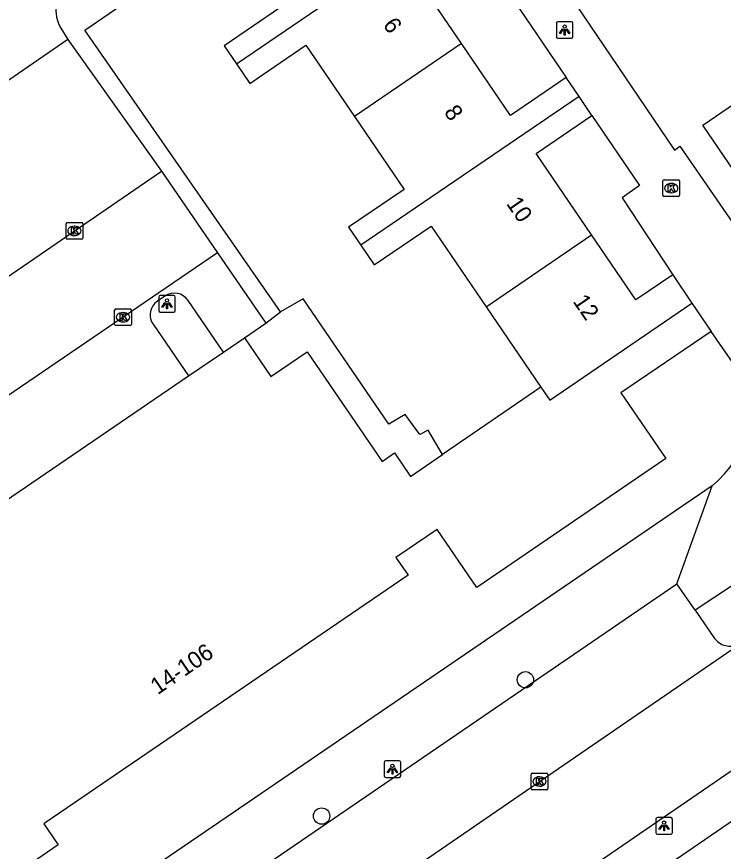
# Model space of a CAD drawing. Extents: x 157466 to 158888, y 383063 to 384677.
# Drawn here: x 158400.9 to 158443.3, y 383786.1 to 383836.2 of the extents above; entities that cross this region are included whole.
import ezdxf

# ---------------------------------------------------------------- set-up
doc = ezdxf.new("R2010")
doc.units = 0
for name, color, linetype in [('IMGEO_Boom', 7, 'Continuous'), ('IMGEO_Kolk', 7, 'Continuous'), ('IMGEO_Lichtpunt', 7, 'Continuous'), ('IMGEO_Pand', 7, 'Continuous'), ('IMGEO_Pand_nummerreeks', 7, 'Continuous'), ('IMGEO_Parkeervlak_open', 7, 'Continuous'), ('IMGEO_Rijbaan_lokaal_open', 7, 'Continuous'), ('IMGEO_Voetpad_open', 7, 'Continuous')]:
    doc.layers.add(name, color=color, linetype=linetype)

msp = doc.modelspace()

# ---------------------------------------------------------------- linework, layer by layer
at = {"layer": 'IMGEO_Boom'}
for centre in [(158431.47, 383796.371), (158419.242, 383788.198)]:
    msp.add_circle(centre, 0.489, dxfattribs=at)
at = {"layer": 'IMGEO_Kolk'}
for p, q in [((158439.718, 383825.444), (158439.718, 383826.296)), ((158439.793, 383826.37), (158440.645, 383826.37)), ((158440.206, 383826.15), (158440.231, 383826.15)), ((158440.719, 383826.296), (158440.719, 383825.444)), ((158440.229, 383825.59), (158440.204, 383825.59)), ((158440.645, 383825.37), (158439.793, 383825.37)), ((158403.906, 383822.873), (158403.906, 383823.725)), ((158403.981, 383823.799), (158404.833, 383823.799)), ((158404.394, 383823.579), (158404.419, 383823.579)), ((158404.907, 383823.725), (158404.907, 383822.873)), ((158404.417, 383823.019), (158404.392, 383823.019)), ((158404.833, 383822.799), (158403.981, 383822.799)), ((158406.823, 383817.693), (158406.823, 383818.545)), ((158406.898, 383818.619), (158407.75, 383818.619)), ((158407.824, 383818.545), (158407.824, 383817.693)), ((158407.311, 383818.399), (158407.336, 383818.399)), ((158407.75, 383817.619), (158406.898, 383817.619)), ((158407.334, 383817.839), (158407.309, 383817.839)), ((158431.814, 383789.845), (158431.814, 383790.697)), ((158431.889, 383790.771), (158432.741, 383790.771)), ((158432.302, 383790.551), (158432.327, 383790.551)), ((158432.815, 383790.697), (158432.815, 383789.845)), ((158432.325, 383789.991), (158432.3, 383789.991)), ((158432.741, 383789.771), (158431.889, 383789.771))]:
    msp.add_line(p, q, dxfattribs=at)
for points in [[(158439.718, 383825.444), (158439.718, 383826.296)], [(158439.793, 383826.37), (158440.645, 383826.37)], [(158440.039, 383826.07), (158440.162, 383826.07), (158440.162, 383825.919), (158440.292, 383826.07), (158440.456, 383826.07), (158440.31, 383825.919), (158440.463, 383825.67), (158440.311, 383825.67), (158440.226, 383825.834), (158440.162, 383825.767), (158440.162, 383825.67), (158440.039, 383825.67), (158440.039, 383826.07)], [(158440.719, 383826.296), (158440.719, 383825.444)], [(158440.645, 383825.37), (158439.793, 383825.37)], [(158403.906, 383822.873), (158403.906, 383823.725)], [(158403.981, 383823.799), (158404.833, 383823.799)], [(158404.907, 383823.725), (158404.907, 383822.873)], [(158404.227, 383823.499), (158404.35, 383823.499), (158404.35, 383823.348), (158404.48, 383823.499), (158404.644, 383823.499), (158404.498, 383823.348), (158404.651, 383823.099), (158404.499, 383823.099), (158404.414, 383823.263), (158404.35, 383823.196), (158404.35, 383823.099), (158404.227, 383823.099), (158404.227, 383823.499)], [(158404.833, 383822.799), (158403.981, 383822.799)], [(158406.823, 383817.693), (158406.823, 383818.545)], [(158406.898, 383818.619), (158407.75, 383818.619)], [(158407.824, 383818.545), (158407.824, 383817.693)], [(158407.144, 383818.319), (158407.267, 383818.319), (158407.267, 383818.168), (158407.397, 383818.319), (158407.561, 383818.319), (158407.415, 383818.168), (158407.568, 383817.919), (158407.416, 383817.919), (158407.331, 383818.083), (158407.267, 383818.016), (158407.267, 383817.919), (158407.144, 383817.919), (158407.144, 383818.319)], [(158407.75, 383817.619), (158406.898, 383817.619)], [(158431.814, 383789.845), (158431.814, 383790.697)], [(158431.889, 383790.771), (158432.741, 383790.771)], [(158432.135, 383790.471), (158432.258, 383790.471), (158432.258, 383790.32), (158432.388, 383790.471), (158432.552, 383790.471), (158432.406, 383790.32), (158432.559, 383790.071), (158432.407, 383790.071), (158432.322, 383790.235), (158432.258, 383790.168), (158432.258, 383790.071), (158432.135, 383790.071), (158432.135, 383790.471)], [(158432.815, 383790.697), (158432.815, 383789.845)], [(158432.741, 383789.771), (158431.889, 383789.771)]]:
    msp.add_lwpolyline(points, dxfattribs=at)
for centre, start, end in [((158439.795, 383826.294), 91.552, 178.448), ((158439.795, 383826.294), 91.552, 178.448), ((158440.643, 383826.294), 1.552, 88.448), ((158440.643, 383826.294), 1.552, 88.448), ((158439.795, 383825.446), 181.552, 268.448), ((158439.795, 383825.446), 181.552, 268.448), ((158440.643, 383825.446), 271.552, 358.448), ((158440.643, 383825.446), 271.552, 358.448), ((158403.983, 383823.723), 91.552, 178.448), ((158403.983, 383823.723), 91.552, 178.448), ((158404.831, 383823.723), 1.552, 88.448), ((158404.831, 383823.723), 1.552, 88.448), ((158403.983, 383822.875), 181.552, 268.448), ((158403.983, 383822.875), 181.552, 268.448), ((158404.831, 383822.875), 271.552, 358.448), ((158404.831, 383822.875), 271.552, 358.448), ((158406.9, 383818.543), 91.552, 178.448), ((158406.9, 383818.543), 91.552, 178.448), ((158407.748, 383818.543), 1.552, 88.448), ((158407.748, 383818.543), 1.552, 88.448), ((158406.9, 383817.695), 181.552, 268.448), ((158406.9, 383817.695), 181.552, 268.448), ((158407.748, 383817.695), 271.552, 358.448), ((158407.748, 383817.695), 271.552, 358.448), ((158431.891, 383790.695), 91.552, 178.448), ((158431.891, 383790.695), 91.552, 178.448), ((158432.739, 383790.695), 1.552, 88.448), ((158432.739, 383790.695), 1.552, 88.448), ((158431.891, 383789.847), 181.552, 268.448), ((158431.891, 383789.847), 181.552, 268.448), ((158432.739, 383789.847), 271.552, 358.448), ((158432.739, 383789.847), 271.552, 358.448)]:
    msp.add_arc(centre, 0.0765, start, end, dxfattribs=at)
for centre, major_axis, ratio, start_param, end_param in [((158440.205, 383825.87), (-0.387, 0.002), 0.722429, 4.712389, 7.853982), ((158440.23, 383825.87), (-0.39, 0.002), 0.717154, 1.570796, 4.712389), ((158404.393, 383823.299), (-0.387, 0.002), 0.722429, 4.712389, 7.853982), ((158404.418, 383823.299), (-0.39, 0.002), 0.717154, 1.570796, 4.712389), ((158407.31, 383818.119), (-0.387, 0.002), 0.722429, 4.712389, 7.853982), ((158407.335, 383818.119), (-0.39, 0.002), 0.717154, 1.570796, 4.712389), ((158432.301, 383790.271), (-0.387, 0.002), 0.722429, 4.712389, 7.853982), ((158432.326, 383790.271), (-0.39, 0.002), 0.717154, 1.570796, 4.712389)]:
    msp.add_ellipse(centre, major_axis=major_axis, ratio=ratio, start_param=start_param, end_param=end_param, dxfattribs=at)
at = {"layer": 'IMGEO_Lichtpunt'}
for p, q in [((158433.325, 383835.758), (158433.325, 383834.951)), ((158433.325, 383835.758), (158433.325, 383834.951)), ((158434.227, 383835.853), (158433.419, 383835.853)), ((158434.227, 383835.853), (158433.419, 383835.853)), ((158434.321, 383834.951), (158434.321, 383835.758)), ((158434.321, 383834.951), (158434.321, 383835.758)), ((158433.419, 383834.857), (158434.227, 383834.857)), ((158433.419, 383834.857), (158434.227, 383834.857)), ((158409.465, 383819.335), (158409.465, 383818.528)), ((158409.465, 383819.335), (158409.465, 383818.528)), ((158410.367, 383819.43), (158409.559, 383819.43)), ((158410.367, 383819.43), (158409.559, 383819.43)), ((158410.461, 383818.528), (158410.461, 383819.335)), ((158410.461, 383818.528), (158410.461, 383819.335)), ((158409.559, 383818.434), (158410.367, 383818.434)), ((158409.559, 383818.434), (158410.367, 383818.434)), ((158423.895, 383791.514), (158423.087, 383791.514)), ((158423.895, 383791.514), (158423.087, 383791.514)), ((158422.993, 383791.419), (158422.993, 383790.612)), ((158422.993, 383791.419), (158422.993, 383790.612)), ((158423.989, 383790.612), (158423.989, 383791.419)), ((158423.989, 383790.612), (158423.989, 383791.419)), ((158423.087, 383790.518), (158423.895, 383790.518)), ((158423.087, 383790.518), (158423.895, 383790.518)), ((158439.292, 383788.013), (158439.292, 383787.206)), ((158439.292, 383788.013), (158439.292, 383787.206)), ((158440.194, 383788.108), (158439.386, 383788.108)), ((158440.194, 383788.108), (158439.386, 383788.108)), ((158440.288, 383787.206), (158440.288, 383788.013)), ((158440.288, 383787.206), (158440.288, 383788.013)), ((158439.386, 383787.112), (158440.194, 383787.112)), ((158439.386, 383787.112), (158440.194, 383787.112))]:
    msp.add_line(p, q, dxfattribs=at)
for points in [[(158433.699, 383835.422), (158433.738, 383835.394), (158433.55, 383835.132), (158433.512, 383835.159), (158433.699, 383835.422)], [(158433.801, 383835.374), (158433.848, 383835.374), (158433.848, 383835.052), (158433.801, 383835.052), (158433.801, 383835.374)], [(158433.911, 383835.394), (158433.949, 383835.421), (158434.136, 383835.159), (158434.097, 383835.131), (158433.911, 383835.394)], [(158409.839, 383818.999), (158409.878, 383818.971), (158409.69, 383818.709), (158409.652, 383818.736), (158409.839, 383818.999)], [(158410.051, 383818.971), (158410.089, 383818.998), (158410.276, 383818.736), (158410.237, 383818.708), (158410.051, 383818.971)], [(158409.941, 383818.951), (158409.988, 383818.951), (158409.988, 383818.629), (158409.941, 383818.629), (158409.941, 383818.951)], [(158423.367, 383791.083), (158423.406, 383791.055), (158423.218, 383790.793), (158423.18, 383790.82), (158423.367, 383791.083)], [(158423.469, 383791.035), (158423.516, 383791.035), (158423.516, 383790.713), (158423.469, 383790.713), (158423.469, 383791.035)], [(158423.579, 383791.055), (158423.617, 383791.082), (158423.804, 383790.82), (158423.765, 383790.792), (158423.579, 383791.055)], [(158439.666, 383787.677), (158439.705, 383787.649), (158439.517, 383787.387), (158439.479, 383787.414), (158439.666, 383787.677)], [(158439.768, 383787.629), (158439.815, 383787.629), (158439.815, 383787.307), (158439.768, 383787.307), (158439.768, 383787.629)], [(158439.878, 383787.649), (158439.916, 383787.676), (158440.103, 383787.414), (158440.064, 383787.386), (158439.878, 383787.649)]]:
    msp.add_lwpolyline(points, dxfattribs=at)
for centre in [(158433.824, 383835.556), (158409.964, 383819.133), (158423.492, 383791.217), (158439.791, 383787.811)]:
    msp.add_circle(centre, 0.0994, dxfattribs=at)
for centre, start, end in [((158433.419, 383835.758), 90, 180), ((158433.419, 383835.758), 90, 180), ((158434.227, 383835.758), 0, 90), ((158434.227, 383835.758), 0, 90), ((158433.419, 383834.951), 180, 270), ((158433.419, 383834.951), 180, 270), ((158434.227, 383834.951), 270, 0), ((158434.227, 383834.951), 270, 360), ((158409.559, 383819.335), 90, 180), ((158409.559, 383819.335), 90, 180), ((158410.367, 383819.335), 0, 90), ((158410.367, 383819.335), 0, 90), ((158409.559, 383818.528), 180, 270), ((158409.559, 383818.528), 180, 270), ((158410.367, 383818.528), 270, 0), ((158410.367, 383818.528), 270, 360), ((158423.087, 383791.419), 90, 180), ((158423.087, 383791.419), 90, 180), ((158423.895, 383791.419), 0, 90), ((158423.895, 383791.419), 0, 90), ((158423.087, 383790.612), 180, 270), ((158423.087, 383790.612), 180, 270), ((158423.895, 383790.612), 270, 0), ((158423.895, 383790.612), 270, 360), ((158439.386, 383788.013), 90, 180), ((158439.386, 383788.013), 90, 180), ((158440.194, 383788.013), 0, 90), ((158440.194, 383788.013), 0, 90), ((158439.386, 383787.206), 180, 270), ((158439.386, 383787.206), 180, 270), ((158440.194, 383787.206), 270, 0), ((158440.194, 383787.206), 270, 360)]:
    msp.add_arc(centre, 0.0946, start, end, dxfattribs=at)
at = {"layer": 'IMGEO_Pand'}
for points in [[(158478.224, 383854.282), (158477.81, 383854.89), (158478.271, 383855.204), (158477.039, 383857.01), (158479.58, 383858.744), (158483.71, 383861.562), (158491.044, 383850.813), (158484.439, 383846.306), (158484.117, 383846.778), (158447.456, 383821.813), (158442.113, 383829.643), (158446.244, 383832.462), (158478.224, 383854.282)], [(158414.129, 383833.314), (158427.275, 383842.274)], [(158413.683, 383841.28), (158416.791, 383836.723), (158413.387, 383834.401), (158414.129, 383833.314)], [(158427.642, 383834.547), (158424.699, 383838.862), (158428.045, 383841.145)], [(158427.642, 383834.547), (158421.214, 383830.164)], [(158433.911, 383832.502), (158430.584, 383830.233), (158427.642, 383834.547)], [(158414.129, 383833.314), (158414.93, 383832.139), (158418.299, 383834.437), (158421.214, 383830.164)], [(158434.685, 383831.366), (158433.911, 383832.502)], [(158434.685, 383831.366), (158421.595, 383822.444)], [(158435.459, 383830.231), (158434.685, 383831.366)], [(158421.214, 383830.164), (158424.197, 383825.79), (158420.863, 383823.516), (158421.595, 383822.444)], [(158435.44, 383823.07), (158432.113, 383827.949), (158435.459, 383830.231)], [(158421.595, 383822.444), (158422.404, 383821.257), (158425.812, 383823.582), (158429.108, 383818.75)], [(158429.108, 383818.75), (158435.44, 383823.07)], [(158440.305, 383820.668), (158438.103, 383819.166), (158435.44, 383823.07)], [(158440.305, 383820.668), (158441.462, 383818.971)], [(158429.108, 383818.75), (158432.403, 383813.919)], [(158432.403, 383813.919), (158432.927, 383813.15), (158441.462, 383818.971)], [(158441.462, 383818.971), (158442.619, 383817.275)], [(158442.619, 383817.275), (158437.202, 383813.58), (158439.887, 383809.644), (158428.548, 383801.911), (158426.177, 383805.388), (158423.704, 383803.702), (158424.427, 383802.642), (158402.712, 383787.832), (158402.577, 383787.74), (158403.44, 383786.474), (158400.485, 383784.46), (158400.653, 383784.214), (158401.312, 383783.247), (158389.931, 383775.485), (158388.503, 383777.577), (158386.41, 383776.149), (158383.749, 383780.051)], [(158413.36, 383816.032), (158414.615, 383816.888)], [(158414.615, 383816.888), (158416.2, 383814.564), (158418.382, 383816.052), (158422.868, 383809.474), (158423.611, 383809.981), (158424.569, 383808.576), (158426.503, 383809.895)], [(158411.257, 383814.598), (158413.36, 383816.032)], [(158394.521, 383803.185), (158411.257, 383814.598)], [(158432.403, 383813.919), (158426.503, 383809.895)]]:
    msp.add_lwpolyline(points, dxfattribs=at)
at = {"layer": 'IMGEO_Parkeervlak_open'}
for points in [[(158409.84, 383819.395), (158409.389, 383819.087)], [(158413.36, 383816.032), (158411.227, 383819.135)], [(158409.126, 383817.697), (158411.257, 383814.598)]]:
    msp.add_lwpolyline(points, dxfattribs=at)
for centre, radius, start, end in [((158410.403, 383818.567), 1.001, 34.5631, 124.2026), ((158409.947, 383818.262), 0.996, 124.052, 214.5196)]:
    msp.add_arc(centre, radius, start, end, dxfattribs=at)
at = {"layer": 'IMGEO_Rijbaan_lokaal_open'}
for points in [[(158417.807, 383850.448), (158417.28, 383849.814), (158405.7, 383839.683), (158403.952, 383838.104), (158403.819, 383837.96), (158403.699, 383837.804), (158403.593, 383837.638), (158403.503, 383837.464), (158403.428, 383837.282), (158403.371, 383837.094), (158403.33, 383836.902), (158403.306, 383836.707), (158403.3, 383836.51), (158403.312, 383836.314), (158403.341, 383836.12), (158403.387, 383835.929), (158403.451, 383835.743), (158403.53, 383835.563), (158403.585, 383835.46), (158404.013, 383834.782)], [(158404.013, 383834.782), (158389.835, 383825.015)], [(158390.494, 383819.62), (158393.327, 383815.709), (158409.632, 383826.877)], [(158409.632, 383826.877), (158412.995, 383821.985)], [(158412.995, 383821.985), (158391.594, 383807.401)], [(158394.384, 383764.411), (158407.233, 383773.047), (158444.242, 383798.459)], [(158447.639, 383793.508), (158438.021, 383786.908), (158394.268, 383756.934)]]:
    msp.add_lwpolyline(points, dxfattribs=at)
at = {"layer": 'IMGEO_Voetpad_open'}
for points in [[(158403.479, 383880.004), (158404.851, 383878.41), (158406.958, 383876.246), (158411.036, 383871.909), (158430.803, 383851.097), (158426.813, 383848.24), (158440.405, 383828.146), (158440.739, 383828.38), (158449.308, 383815.94)], [(158416.783, 383818.454), (158405.033, 383835.334), (158413.683, 383841.28)], [(158428.045, 383841.145), (158433.911, 383832.502)], [(158512.351, 383834.835), (158500, 383826.37), (158395.719, 383754.902)], [(158404.013, 383834.782), (158409.632, 383826.877)], [(158435.459, 383830.231), (158438.317, 383826.023), (158437.275, 383825.292), (158440.305, 383820.668)], [(158412.995, 383821.985), (158415.898, 383817.763)], [(158426.503, 383809.895), (158425.626, 383811.351), (158425.141, 383811.08), (158424.253, 383812.296), (158423.282, 383811.714), (158418.126, 383819.23), (158416.783, 383818.454)], [(158415.898, 383817.763), (158416.783, 383818.454)], [(158414.615, 383816.888), (158415.898, 383817.763)], [(158444.836, 383812.806), (158444.781, 383813.291), (158444.684, 383813.768), (158444.544, 383814.235), (158444.363, 383814.688), (158444.26, 383814.902), (158442.619, 383817.275)], [(158442.667, 383807.999), (158443.06, 383808.341), (158443.421, 383808.718), (158443.747, 383809.124), (158444.036, 383809.559), (158444.284, 383810.017), (158444.46, 383810.417), (158444.62, 383810.877), (158444.739, 383811.35), (158444.815, 383811.832), (158444.847, 383812.319), (158444.836, 383812.806)], [(158442.667, 383807.999), (158390.257, 383772.256)], [(158440.564, 383802.129), (158442.667, 383807.999)], [(158445.139, 383802.839), (158441.649, 383800.55)], [(158392.331, 383769.184), (158440.564, 383802.129)], [(158441.649, 383800.55), (158440.564, 383802.129)], [(158441.649, 383800.55), (158442.777, 383798.908), (158442.842, 383798.822), (158442.914, 383798.743), (158442.993, 383798.67), (158443.078, 383798.605), (158443.169, 383798.547), (158443.264, 383798.498), (158443.363, 383798.457), (158443.466, 383798.426), (158443.571, 383798.404), (158443.678, 383798.391), (158443.785, 383798.388), (158443.892, 383798.394), (158443.998, 383798.41), (158444.103, 383798.436), (158444.204, 383798.47), (158444.302, 383798.514), (158444.396, 383798.566), (158444.418, 383798.58)]]:
    msp.add_lwpolyline(points, dxfattribs=at)

# ---------------------------------------------------------------- texts
at = {"layer": 'IMGEO_Pand_nummerreeks'}
for s, rotation, p in [('6', 304.5841, (158422.886, 383835.664)), ('8', 304.5841, (158426.55, 383830.426)), ('10', 304.5841, (158430.287, 383824.935)), ('12', 304.5841, (158434.282, 383819.071)), ('14-106', 34.2915, (158409.405, 383795.448))]:
    msp.add_text(s, height=1, rotation=rotation, dxfattribs=at).set_placement(p)

doc.saveas('drawing.dxf')
